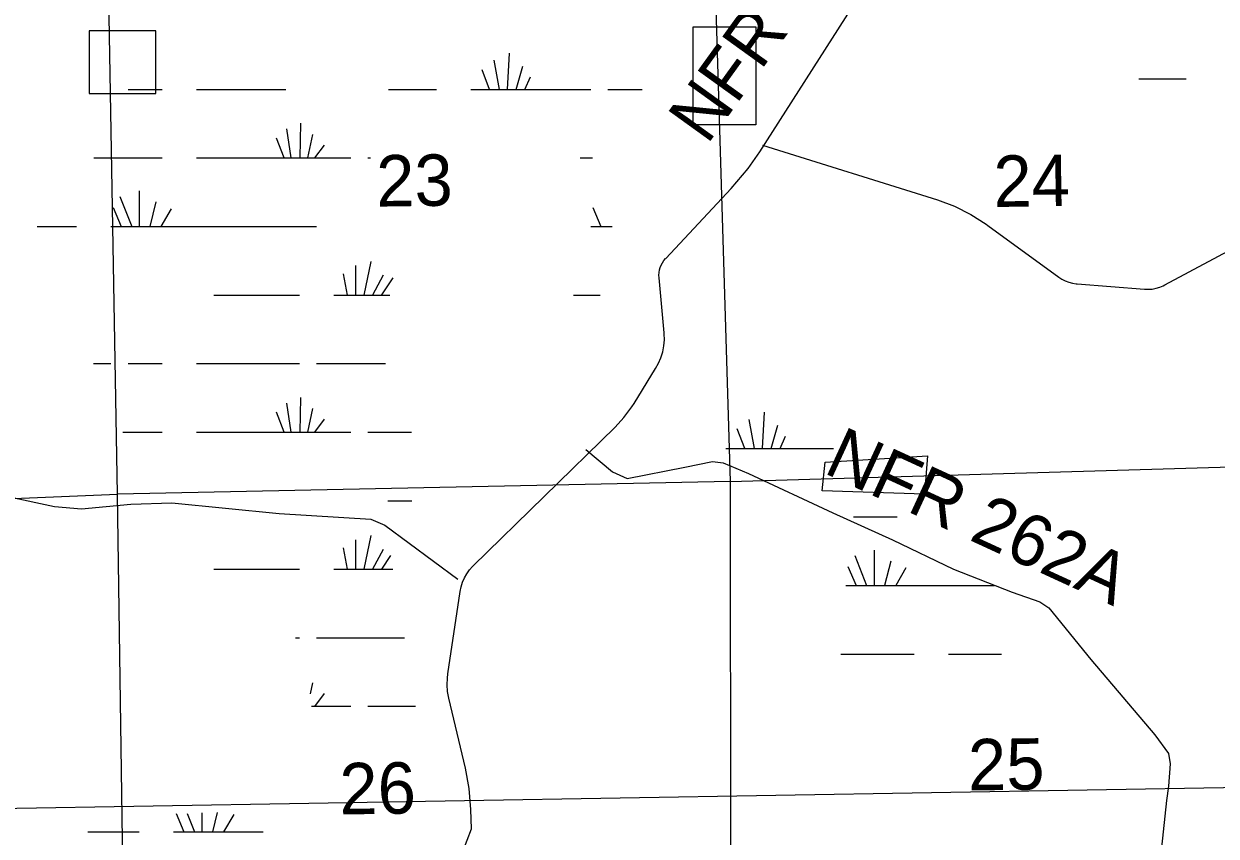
# Model space of a CAD drawing. Extents: x 2480962 to 2688785, y 277103 to 599240.
# Drawn here: x 2569158 to 2579595, y 504908 to 512018 of the extents above; entities that cross this region are included whole.
import ezdxf

# ---------------------------------------------------------------- set-up
doc = ezdxf.new("R2010")
doc.units = 0
for name, color, linetype in [('Divided_Highway', 7, 'Continuous'), ('Level 31', 7, 'Continuous'), ('Local Roads Improved', 7, 'Continuous'), ('Local Roads Related Text', 7, 'Continuous'), ('Section Lines', 7, 'Continuous'), ('Section Numbers', 7, 'Continuous'), ('Swamps', 7, 'Continuous')]:
    doc.layers.add(name, color=color, linetype=linetype)

msp = doc.modelspace()

# ---------------------------------------------------------------- linework, layer by layer
at = {"layer": 'Divided_Highway'}
msp.add_line((2559790.472, 504995.814), (2599203.547, 505666.246), dxfattribs=at)
at = {"layer": 'Level 31'}
for points in [[(2569729.711, 511408.742), (2570313.196, 511408.742), (2570313.196, 511958.265), (2569729.711, 511958.265)], [(2575015.397, 511992.61), (2575564.559, 511992.61), (2575564.559, 511133.98), (2575015.397, 511133.98)], [(2576145.068, 507929.913), (2576173.046, 508181.889), (2577068.336, 508237.884), (2577040.358, 507901.916)]]:
    msp.add_lwpolyline(points, close=True, dxfattribs=at)
at = {"layer": 'Local Roads Improved'}
for p, q in [((2575601.761, 510899.164), (2576599.15, 512459.772)), ((2575623.636, 510957.713), (2577155.86, 510476.954)), ((2574776.066, 509964.761), (2575350.16, 510575.921)), ((2577597.133, 510254.306), (2578216.759, 509802.016)), ((2579145.582, 509733.005), (2579860.979, 510116.363)), ((2574762.582, 509314.736), (2574718.226, 509796.534)), ((2578378.99, 509741.969), (2578967.659, 509695.688)), ((2574499.306, 508695.717), (2574688.411, 509000.477)), ((2573091.719, 507274.881), (2574332.758, 508488.089)), ((2572869.149, 506329.252), (2572976.64, 507049.686)), ((2573023.715, 505502.113), (2572878.089, 506117.333)), ((2573074.813, 504972.962), (2573070.392, 505142.908)), ((2571865.435, 501739.429), (2573074.813, 504972.962))]:
    msp.add_line(p, q, dxfattribs=at)
for points in [[(2575350.16, 510575.921), (2575499.623, 510752.73), (2575601.761, 510899.164)], [(2577155.86, 510476.954), (2577305.019, 510421.422), (2577447.556, 510350.605), (2577581.908, 510265.275), (2577597.133, 510254.306)], [(2574718.226, 509796.534), (2574717.331, 509819.198), (2574718.81, 509841.831), (2574722.648, 509864.186), (2574728.801, 509886.017), (2574737.201, 509907.086), (2574747.759, 509927.16), (2574760.357, 509946.023), (2574774.858, 509963.464), (2574776.066, 509964.761)], [(2578216.759, 509802.016), (2578244.577, 509783.862), (2578274.141, 509768.716), (2578305.126, 509756.743), (2578337.193, 509748.075), (2578369.99, 509742.805), (2578378.99, 509741.969)], [(2578967.659, 509695.688), (2579001.465, 509694.806), (2579035.178, 509697.462), (2579068.429, 509703.628), (2579100.853, 509713.235), (2579132.096, 509726.179), (2579145.582, 509733.005)], [(2574688.411, 509000.477), (2574714.03, 509047.041), (2574734.642, 509096.029), (2574750.022, 509146.902), (2574759.998, 509199.105), (2574764.463, 509252.064), (2574763.369, 509305.201), (2574762.582, 509314.736)], [(2574332.758, 508488.089), (2574411.149, 508573.19), (2574480.215, 508666.019), (2574499.306, 508695.717)], [(2574076.407, 508292.44), (2574310.213, 508096.21), (2574439.641, 508037.758), (2574944.829, 508137.961), (2575186.985, 508188.062), (2575278.838, 508175.537), (2575500.118, 508083.685), (2576239.112, 507737.151), (2576761, 507503.345), (2577295.414, 507244.488), (2577808.952, 507044.083), (2578051.109, 506960.581), (2578130.436, 506906.304), (2578497.845, 506455.393), (2579057.309, 505795.726), (2579178.387, 505632.897), (2579190.913, 505541.045), (2579178.387, 505344.814), (2579161.687, 505219.561), (2579115.761, 504810.401)], [(2569033.293, 507877.291), (2569424.628, 507794.905), (2569661.489, 507774.308), (2570094.017, 507815.501), (2570454.457, 507825.8), (2571391.602, 507733.115), (2572194.869, 507681.623), (2572318.449, 507630.132), (2572956.943, 507156.41)], [(2572976.64, 507049.686), (2572984.911, 507090.389), (2572997.391, 507130.005), (2573013.945, 507168.099), (2573034.388, 507204.254), (2573058.5, 507238.074), (2573086.014, 507269.189), (2573091.719, 507274.881)], [(2572878.089, 506117.333), (2572867.576, 506175.081), (2572863.157, 506233.611), (2572864.882, 506292.282), (2572869.149, 506329.252)], [(2573070.392, 505142.908), (2573055.985, 505326.351), (2573023.715, 505502.113)]]:
    msp.add_lwpolyline(points, dxfattribs=at)
at = {"layer": 'Section Lines'}
for p, q in [((2575180.081, 513260.41), (2575340.459, 508012.28)), ((2569978.119, 507900.972), (2569885.882, 513170.735)), ((2575340.459, 508012.276), (2580582.261, 508164.859)), ((2575340.459, 508012.28), (2569978.119, 507900.972)), ((2575340.459, 508012.28), (2575340.575, 507848.862)), ((2575340.459, 508012.276), (2575344.263, 502664.415)), ((2564678.735, 507684.106), (2569978.119, 507900.972)), ((2570055.571, 502552.836), (2569978.119, 507900.972))]:
    msp.add_line(p, q, dxfattribs=at)
at = {"layer": 'Swamps'}
for p, q in [((2573391.23, 511444.723), (2573408.466, 511760.796)), ((2573320.23, 511444.772), (2573273.975, 511699.152)), ((2573467.916, 511444.902), (2573526.148, 511648.721)), ((2573235.156, 511444.86), (2573169.683, 511616.724)), ((2573544.512, 511444.825), (2573593.395, 511553.458)), ((2570069.725, 511444.64), (2570369.724, 511444.645)), ((2570669.724, 511444.649), (2571269.723, 511444.658)), ((2573069.721, 511444.686), (2574119.72, 511444.702)), ((2574269.72, 511444.704), (2574569.719, 511444.709)), ((2571575.894, 510844.684), (2571581.622, 511148.397)), ((2571435.411, 510845.65), (2571369.339, 511018.443)), ((2571497.732, 510844.728), (2571458.338, 511097.962)), ((2571642.993, 510844.476), (2571685.878, 511050.327)), ((2571705.189, 510844.169), (2571788.967, 510957.87)), ((2569769.733, 510844.637), (2570369.732, 510844.647)), ((2570669.732, 510844.651), (2571269.731, 510844.66)), ((2571269.731, 510844.66), (2572019.73, 510844.672)), ((2569999.244, 510507.317), (2570102.265, 510244.645)), ((2570168.395, 510555.649), (2570168.399, 510244.646)), ((2569938.834, 510410.658), (2570009.647, 510244.643)), ((2570313.383, 510458.993), (2570259.774, 510244.546)), ((2570446.288, 510398.584), (2570356.57, 510244.777)), ((2574138.828, 510410.723), (2574209.641, 510244.708)), ((2569919.74, 510244.642), (2571269.738, 510244.662)), ((2571269.738, 510244.662), (2571719.738, 510244.669)), ((2572060.687, 509903.238), (2572060.691, 509644.677)), ((2572193.592, 509939.486), (2572134.655, 509644.783)), ((2571951.947, 509830.742), (2571989.159, 509644.697)), ((2572302.333, 509818.666), (2572208.327, 509644.079)), ((2570819.746, 509644.657), (2571269.746, 509644.664)), ((2571269.746, 509644.664), (2571569.745, 509644.669)), ((2570069.755, 509044.648), (2570369.754, 509044.653)), ((2570669.754, 509044.657), (2571269.753, 509044.666)), ((2571269.753, 509044.666), (2571569.753, 509044.671)), ((2571575.924, 508444.692), (2571581.651, 508748.405)), ((2571435.44, 508445.658), (2571369.369, 508618.451)), ((2571497.762, 508444.736), (2571458.368, 508697.969)), ((2571643.023, 508444.484), (2571685.908, 508650.335)), ((2575624.157, 508301.879), (2575641.394, 508617.952)), ((2571705.219, 508444.177), (2571788.997, 508557.878)), ((2575553.157, 508301.928), (2575506.902, 508556.308)), ((2570669.761, 508444.659), (2571269.761, 508444.668)), ((2571269.761, 508444.668), (2572019.76, 508444.68)), ((2575468.084, 508302.015), (2575402.611, 508473.88)), ((2575700.843, 508302.058), (2575759.076, 508505.877)), ((2575777.439, 508301.981), (2575826.323, 508410.614)), ((2576419.466, 507701.861), (2576802.654, 507701.867)), ((2572060.717, 507503.246), (2572060.72, 507244.684)), ((2572193.622, 507539.494), (2572134.684, 507244.791)), ((2571951.977, 507430.75), (2571989.189, 507244.705)), ((2572302.363, 507418.674), (2572208.357, 507244.087)), ((2576432.166, 507364.538), (2576535.187, 507101.865)), ((2576601.317, 507412.869), (2576601.321, 507101.866)), ((2576371.756, 507267.879), (2576442.569, 507101.864)), ((2576746.305, 507316.214), (2576692.696, 507101.766)), ((2570819.776, 507244.665), (2571269.776, 507244.672)), ((2571269.776, 507244.672), (2571569.775, 507244.677)), ((2576879.21, 507255.805), (2576789.492, 507101.998)), ((2576308.727, 506501.864), (2576952.668, 506501.873)), ((2577252.668, 506501.878), (2577702.667, 506501.885)), ((2571705.249, 506044.185), (2571789.026, 506157.886)), ((2570994.806, 505098.704), (2570905.088, 504944.897)), ((2569718.259, 504944.75), (2570168.258, 504944.757))]:
    msp.add_line(p, q, dxfattribs=at)
for points in [[(2578917.705, 511537.745), (2579333.454, 511537.752)], [(2571269.723, 511444.658), (2571452.005, 511444.661)], [(2572349.583, 511444.675), (2572769.721, 511444.681)], [(2572169.73, 510844.674), (2572192.071, 510844.675)], [(2574027.347, 510844.703), (2574136.404, 510844.704)], [(2569273.738, 510244.632), (2569619.74, 510244.637)], [(2574119.735, 510244.706), (2574306.453, 510244.709)], [(2572386.909, 509794.502), (2572287.591, 509645.522)], [(2571869.745, 509644.674), (2572362.43, 509644.681)], [(2573969.742, 509644.706), (2574203.117, 509644.709)], [(2569766.587, 509044.643), (2569919.755, 509044.646)], [(2571719.753, 509044.673), (2572324.095, 509044.683)], [(2570024.295, 508444.649), (2570369.762, 508444.654)], [(2572169.759, 508444.682), (2572551.26, 508444.688)], [(2575302.649, 508301.842), (2576244.674, 508301.856)], [(2572342.449, 507844.687), (2572555.363, 507844.69)], [(2572366.528, 507363.894), (2572287.621, 507245.53)], [(2571869.775, 507244.682), (2572387.076, 507244.689)], [(2576352.662, 507101.862), (2577655.122, 507101.882)], [(2571535.226, 506644.678), (2571569.783, 506644.679)], [(2571719.782, 506644.681), (2572488.5, 506644.693)], [(2577702.667, 506501.885), (2577716.43, 506501.885)], [(2571665.564, 506152.548), (2571685.937, 506250.343)], [(2571676.565, 506044.682), (2572019.789, 506044.688)], [(2572169.789, 506044.69), (2572585.63, 506044.697)], [(2570489.728, 505105.204), (2570558.164, 504944.763)], [(2570586.816, 505107.857), (2570650.782, 504944.764)], [(2570716.914, 505111.412), (2570716.916, 504944.765)], [(2570850.891, 505115.074), (2570808.291, 504944.666)], [(2570468.257, 504944.761), (2571251.565, 504944.773)]]:
    msp.add_lwpolyline(points, dxfattribs=at)

# ---------------------------------------------------------------- texts
at = {"layer": 'Local Roads Related Text'}
for s, rotation, p in [('NFR 237', 54.2277167, (2575139.332, 510953.078)), ('NFR 262A', 335.2899583, (2576146.608, 508092.786))]:
    msp.add_text(s, height=450, rotation=rotation, dxfattribs=at).set_placement(p)
at = {"layer": 'Section Numbers'}
for s, rotation, p in [('23', 0.8220528, (2572245.505, 510418.233)), ('24', 0.8220528, (2577648.503, 510414.755)), ('25', 0.8220611, (2577425.612, 505307.486)), ('26', 0.8220611, (2571922.79, 505097.624))]:
    msp.add_text(s, height=450, rotation=rotation, dxfattribs=at).set_placement(p)

doc.saveas('drawing.dxf')
